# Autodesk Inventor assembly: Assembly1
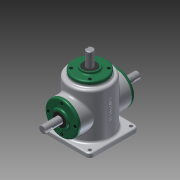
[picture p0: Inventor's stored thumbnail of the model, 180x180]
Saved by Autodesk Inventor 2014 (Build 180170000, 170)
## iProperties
Created: 2015-10
Part Number: Assembly1
Document SubType Name: Assembly
Designer: user
Author: user
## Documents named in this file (14)
- C:\Users\user\Desktop\451008V1004\Assembly1.iam
- C:\Users\user\Desktop\451008V1004\본체.ipt
- C:\Users\user\Desktop\451008V1004\커버.ipt
- C:\Users\user\Desktop\451008V1004\메인 축.ipt
- 메인 축.ipt
- C:\Users\user\Desktop\451008V1004\메인 베벨기어.ipt
- C:\Users\user\Desktop\451008V1004\키 5x5.ipt
- C:\Users\user\Desktop\451008V1004\서브 축.ipt
- 서브 축.ipt
- C:\Users\user\Desktop\451008V1004\서브 베벨기어.ipt
- C:\Users\user\Desktop\451008V1004\키 4x4.ipt
- C:\Users\user\Desktop\451008V1004\베어링 6203.ipt
- C:\Users\user\Desktop\451008V1004\오일실.ipt
- C:\Users\user\Desktop\451008V1004\M4.ipt
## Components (12 placed, 1 different names)
1. M4:9
2. M4:10
3. M4:11
4. M4:12
5. M4:1 — Insert:23
6. M4:3
7. M4:4
8. M4:5
9. M4:2 — Insert:24
10. M4:6
11. M4:7
12. M4:8
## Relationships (2: Insert 2)
- Insert:23: M4:1
- Insert:24: M4:2
